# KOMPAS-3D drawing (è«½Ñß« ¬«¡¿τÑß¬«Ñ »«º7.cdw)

Referenced files: 2.cdw
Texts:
  Колесо зубчатое коническое
  Noncommercial version
  Внешний окружной модуль
  mte
  Число зубьев
  Тип зуба
  Прямой
  Исходный контур
  ГОСТ 13754-81
  Угол делительного конуса
  Symbol type A
  Степень точности по ГОСТ 1758-81
  Внешнее конусное расстояние
  Средний делительный диаметр
  Внешняя высота зуба
  Номер чертежа сопрягаемого колеса
  Js9
  Ra3.2
  max
  ОКМА 26.06.0100.03
  Ra1.6
  2. Радиусы закругления 2 мм.
  3. Н14, h14   IT 14/2.
  4. Данные для контроля зубчатого венца выбирают по ГОСТ 1758-81.
  5.   Размер для справок.
  Ra6,3
  ДГТУ
  Кафедра ТМс
  Сталь45 ГОСТ 1050-74
Dimensions and other numbers on the sheet: 3; 80; 75 96'; 8-В; 123,69; 204,0; 10; 0,4; 41,3; 0,025; 12,6; 0,08; 240; 247,95; 36,9; 57; 1,6; 3,2; 4 фаски; 2; 38; 60; 8,5; 40; 4,4; 14 12'; 53,5; 62*; 0,012; 1. 269-302 НВ.; 1:1; 4; 0; 1; 5; 6; 7; 8; 9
